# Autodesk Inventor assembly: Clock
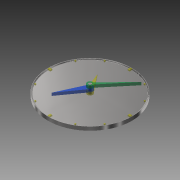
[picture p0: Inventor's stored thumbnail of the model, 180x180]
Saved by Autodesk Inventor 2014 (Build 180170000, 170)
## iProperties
Created: 2013-08
Part Number: Clock
Document SubType Name: Assembly
Designer: ed
RuleStatus: InUse
AfterDocOpen0: ОбновитьВремя
DocClose0: ОбновитьВремя
Часы: 11,000 ч
Минуты: 35,000 мин
Секунды: 7,000 с
Author: ed
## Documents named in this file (6)
- D:\users\ed\stuff\pack_\Workspaces\Workspace\Clock.iam
- D:\users\ed\stuff\pack_\Workspaces\Workspace\disc.ipt
- D:\users\ed\stuff\pack_\Workspaces\Workspace\arrow_h.ipt
- D:\users\ed\stuff\pack_\Workspaces\Workspace\arrow_m.ipt
- D:\users\ed\stuff\pack_\Workspaces\Workspace\arrow_s.ipt
- D:\users\ed\stuff\pack_\Workspaces\Workspace\tick.ipt
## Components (5 placed, 5 different names)
1. disc:1 — Совмещение:1, Совмещение:2, Совмещение:4, Совмещение:6
2. arrow_h:1 — Совмещение:1, Совмещение:2, Угол:1, Совмещение:3
3. arrow_m:1 — Совмещение:3, Совмещение:4, Совмещение:5, Угол:2
4. arrow_s:1 — Совмещение:5, Совмещение:6, Угол:3
5. tick:1 — Заподлицо:1, Совмещение:7, Совмещение:8
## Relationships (12: Mate 8, Angle 3, Flush 1)
- Совмещение:1 [Mate]: disc:1 ↔ arrow_h:1
- Совмещение:2 [Mate]: disc:1 ↔ arrow_h:1
- Угол:1 [Angle]: arrow_h:1
- Совмещение:3 [Mate]: arrow_h:1 ↔ arrow_m:1
- Совмещение:4 [Mate]: disc:1 ↔ arrow_m:1
- Совмещение:5 [Mate]: arrow_m:1 ↔ arrow_s:1
- Совмещение:6 [Mate]: disc:1 ↔ arrow_s:1
- Угол:2 [Angle]: arrow_m:1
- Угол:3 [Angle]: arrow_s:1
- Заподлицо:1 [Flush]: tick:1
- Совмещение:7 [Mate]: tick:1
- Совмещение:8 [Mate]: tick:1
## Named parameters: Часы = 396000 mm, HoursDegree = 330 deg, Минуты = 21000 mm, SecondsDegree = 138 deg, MinutesDegree = -30 deg
